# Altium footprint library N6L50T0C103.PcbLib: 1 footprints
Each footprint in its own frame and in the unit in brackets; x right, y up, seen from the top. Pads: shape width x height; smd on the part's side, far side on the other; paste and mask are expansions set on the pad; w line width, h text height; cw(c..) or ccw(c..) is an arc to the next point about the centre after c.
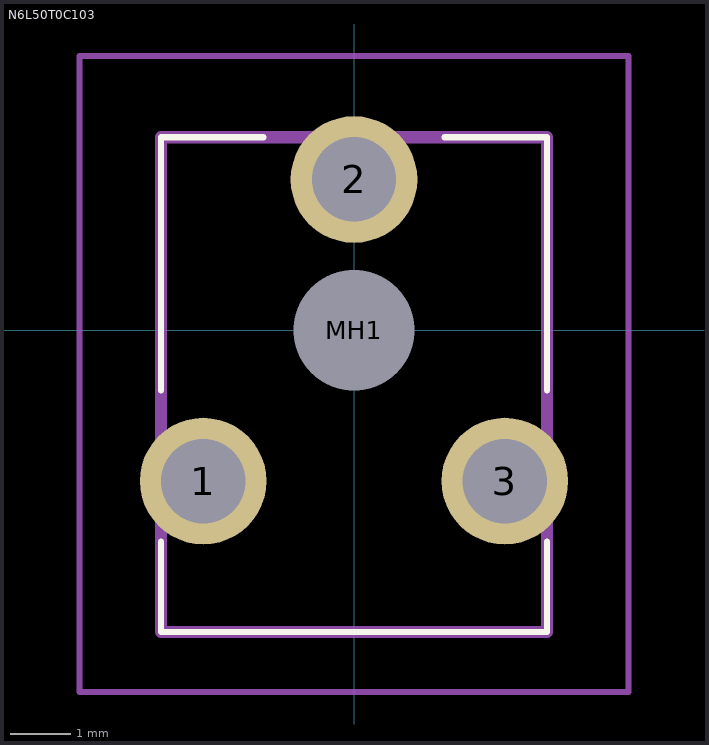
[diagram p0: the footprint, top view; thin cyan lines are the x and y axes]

## N6L50T0C103 [mm]
pads (4):
  round 2.1 hole 1.4: 1(-2.5,-2.5) 2(0,2.5) 3(2.5,-2.5)
  round 1 hole 2 unplated: MH1(0,0)
Top Overlay:
  lines w0.1: -3.2,-3.5 -3.2,-5 3.2,-5 3.2,-3.5 ; -3.2,-1 -3.2,3.2 -1.5,3.2 ; 1.5,3.2 3.2,3.2 3.2,-1
Mechanical 15:
  lines w0.2: -3.2,-5 3.2,-5 3.2,3.2 -3.2,3.2 -3.2,-5
Mechanical 20:
  lines w0.1: -4.55,-6 4.55,-6 4.55,4.55 -4.55,4.55 -4.55,-6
